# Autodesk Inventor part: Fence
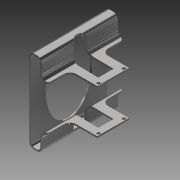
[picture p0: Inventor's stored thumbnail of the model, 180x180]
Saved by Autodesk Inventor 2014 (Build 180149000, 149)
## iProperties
Created: 2008-06
Part Number: Fence
Document SubType Name: Sheet Metal
Designer: tangg
Density: 7.84 g/cm^3
Mass: 20.0562 g
Surface Area: 218.78 cm^2
Volume: 20.0562 cm^3
Stock Number: Fence
Material: Steel, High Strength Low Alloy
Sheet Metal Rule: Default
Appearance: Steel - Polished
Author: tangg
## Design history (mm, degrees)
node "Contour Flange1"
  sketch "Sketch1"
    geometry: L1 (-61.625, 21)-(-88.625, 21); L2 (-96.125, 28.5)-(-96.125, 36.825); L3 (-99.3, 40)-(-102.475, 40); L4 (-105.65, 36.825)-(-105.65, -36.825); L5 (-102.475, -40)-(-99.3, -40); L6 (-96.125, -36.825)-(-96.125, -28.5); L7 (-88.625, -21)-(-61.625, -21); L8 (-88.625, 28.5)-(-88.625, -28.5); A1 r 7.5 centre (-88.625, 28.5) between (-96.125, 28.5) and (-88.625, 21); A2 r 7.5 centre (-88.625, -28.5) between (-88.625, -21) and (-96.125, -28.5); A3 r 3.175 centre (-102.475, 36.825) between (-102.475, 40) and (-105.65, 36.825); A4 r 3.175 centre (-99.3, 36.825) between (-96.125, 36.825) and (-99.3, 40); A5 r 3.175 centre (-102.475, -36.825) between (-105.65, -36.825) and (-102.475, -40); A6 r 3.175 centre (-99.3, -36.825) between (-99.3, -40) and (-96.125, -36.825); 3 further points
    constraints: 16 end point, 12 point on circle, 12 tangent, 6 centre point, 4 equal radius, 2 horizontal alignment, 2 midpoint, 2 perpendicular, 1 collinear, 1 horizontal, 1 parallel
    dimensions: "d0" = 3.175 radius of A3; "d21" = 42 distance between parallel lines of L7 L1; "d22" = 7.5 radius of A1; "d23" = 9.525 distance between parallel lines of L2 L4; "d24" = 7.5 radius of A2 (derived); "d25" = 27 distance of L7.start L7.end; "d26" = 80 distance between parallel lines of L5 L3
sketch "Sketch2"
  geometry: L1 (88.9, -38.1)-(88.9, -22.542); L2 (82.55, -16.192)-(53.975, -16.193); L3 (88.9, 21.908)-(88.9, 39.688); L4 (82.55, 15.558)-(53.975, 15.557); L5 (75.143, -0.318)-(295.098, -0.318); L6 (88.9, -38.1)-(53.975, -38.1); L7 (53.975, 39.688)-(88.9, 39.688); L8 (53.975, -38.1)-(53.975, -16.193); L9 (53.975, 15.557)-(53.975, 39.688); L10 (68.458, 7.655)-(90.487, 7.275); L11 (90.487, 7.275)-(90.487, -7.91); L12 (90.487, -7.91)-(68.458, -7.53); L13 (68.458, -7.53)-(68.458, 7.655); A1 r 6.35 centre (82.55, -22.542) between (88.9, -22.542) and (82.55, -16.192); A2 r 6.35 centre (82.55, 21.907) between (82.55, 15.558) and (88.9, 21.908); 2 further points; 1 other entity
  constraints: 26 end point, 4 point on circle, 4 tangent, 2 centre point, 2 parallel, 1 equal radius, 1 midpoint, 1 point on line, 1 vertical alignment, 2 other
  dimensions: "d11" = 15.875 distance between parallel lines of L5 L2; "d12" = 15.875 distance between parallel lines of L5 L4; "d13" = 6.35 radius of A1
extrude "Extrusion1" cut sketch "Sketch2" stored distance "d14" = 152.4; taper "d15" = 0 deg
sketch "Sketch3"
  geometry: L1 (-76.2, 73.65)-(-76.2, 0) reference; L2 (0, 0)-(0, 73.65) reference; L3 (-76.2, 73.65)-(0, 73.65) reference; L4 (-76.2, 0)-(0, 0) reference; L5 (-76.2, 36.825)-(0, 36.825); L6 (-38.1, 73.65)-(-38.1, 0); 2 further points; 1 other entity
  constraints: 5 midpoint, 4 end point, 2 other
cut "Cut1" sketch "Sketch3" dims "d16" = 1.5875 (= Thickness), "d17" = 0
fillet "Fillet1" dims "d18" = 3.175
sketch "Sketch4"
  geometry: C1 r 1.588 at (19.05, 3.175); C2 r 1.588 at (19.05, 28.575); 1 further point
  constraints: 2 centre point
extrude "Extrusion2" cut sketch "Sketch4" stored distance "d19" = 25.4; taper "d20" = 0 deg
body "Solid1"
face "Plate1" dims "d1" = 1.5875 (= BendReliefWidth), "d2" = 0.79375 (= BendReliefDepth), "d3" = 3.175 (= MinimumRemnant), "d4" = 1.5875 (= BendRadius), "d5" = 76.2, "d6" = 1.5875 (= BendRadius), "d7" = 3.048, "d8" = 6.35 (= CornerReliefSize), "d9" = 1.5875 (= Thickness), "d10" = 1.5875 (= JacobiRadiusSize), "SeamGap" = 0.00508, "Thickness" = 1.5875
bend "Bend1" dims "d1" = 1.5875 (= BendReliefWidth), "d2" = 0.79375 (= BendReliefDepth), "d3" = 3.175 (= MinimumRemnant), "d4" = 1.5875 (= BendRadius), "d6" = 1.5875 (= BendRadius), "d7" = 3.048, "SeamGap" = 0.00508, "Thickness" = 1.5875
feature "Corner1" dims "d7" = 3.048, "d8" = 6.35 (= CornerReliefSize), "d9" = 1.5875 (= Thickness), "d10" = 1.5875 (= JacobiRadiusSize)
other parameters: "KFactor" = 4.4, "BendRadius" = 1.5875 (= Thickness), "BendReliefWidth" = 1.5875 (= Thickness), "BendReliefDepth" = 0.79375 (= 0.5 x Thickness), "CornerReliefSize" = 6.35 (= 4 x Thickness), "MinimumRemnant" = 3.175 (= 2 x Thickness), "TransitionRadius" = 1.5875 (= BendRadius), "JacobiRadiusSize" = 1.5875 (= Thickness), "GapSize" = 1.5875 (= Thickness)
